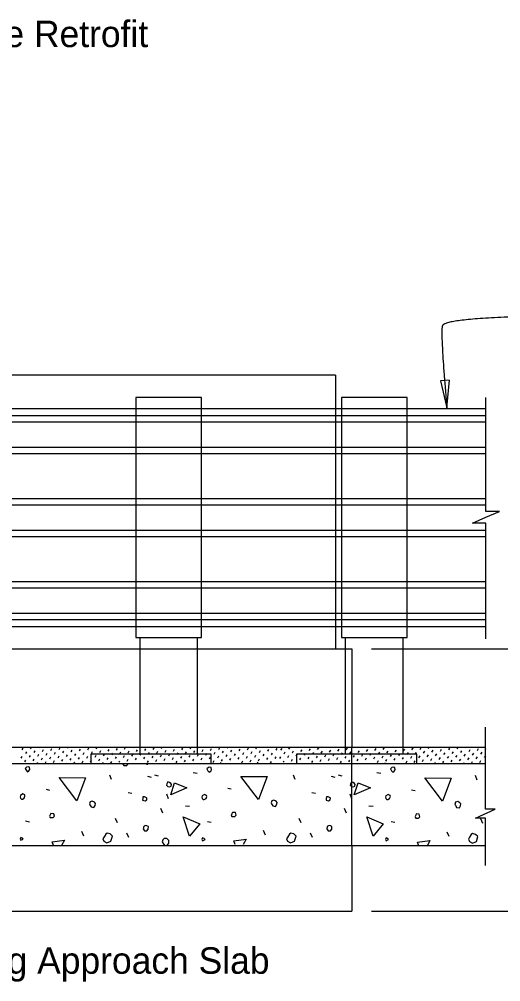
# Model space of a CAD drawing. Extents: x 1.5 to 68.7, y 0 to 31.1.
# Drawn here: x 34.15 to 37.81, y 9.2 to 16.53 of the extents above; entities that cross this region are included whole.
import ezdxf

# ---------------------------------------------------------------- set-up
doc = ezdxf.new("R2010")
doc.units = 0
for name, color, linetype in [('AdhocPoint_dp', 7, 'Continuous'), ('Patterning', 7, 'Continuous'), ('PlotBorder_dp', 7, 'Continuous'), ('SheetBorder_dp', 7, 'Continuous')]:
    doc.layers.add(name, color=color, linetype=linetype)

msp = doc.modelspace()

# ---------------------------------------------------------------- linework, layer by layer
at = {"layer": 'AdhocPoint_dp'}
for p, q in [((36.8263, 11.7345), (39.8006, 11.7345)), ((36.8263, 9.7345), (39.8006, 9.7345))]:
    msp.add_line(p, q, dxfattribs=at)
msp.add_lwpolyline([(37.4003, 13.5697), (37.4212, 13.7799), (37.3508, 13.775)], close=True, dxfattribs=at)
for points in [[(37.6978, 11.8101), (37.6978, 12.6907), (37.5945, 12.6907), (37.6978, 12.7357), (37.8012, 12.7807), (37.6978, 12.7807), (37.6978, 13.649)], [(37.6953, 10.0834), (37.6953, 10.4448), (37.6178, 10.4448), (37.7678, 10.5111), (37.6953, 10.5111), (37.6953, 11.1369)]]:
    msp.add_lwpolyline(points, dxfattribs=at)
msp.add_open_spline([(37.8896, 14.2621), (37.3828, 14.2426), (37.3496, 14.1481), (37.4003, 13.5697)], degree=2, dxfattribs=at)
at = {"layer": 'Patterning'}
for p, q in [((28.9195, 13.5645), (37.6978, 13.5645)), ((29.5771, 13.5123), (37.6978, 13.5123)), ((29.5783, 13.4641), (37.6978, 13.4641)), ((29.5831, 13.2713), (37.6978, 13.2713)), ((29.5842, 13.2231), (37.6978, 13.2231)), ((29.5807, 12.8791), (37.6978, 12.8791)), ((29.5795, 12.8309), (37.6978, 12.8309)), ((29.5747, 12.6381), (37.6978, 12.6381)), ((29.5735, 12.5899), (37.6978, 12.5899)), ((29.5831, 12.1978), (37.6978, 12.1978)), ((29.5842, 12.246), (37.6978, 12.246)), ((29.5771, 11.9567), (37.6978, 11.9567)), ((29.5783, 12.0049), (37.6978, 12.0049)), ((28.9195, 11.9044), (37.6978, 11.9044)), ((35.0654, 10.9324), (35.0654, 11.8211)), ((35.5029, 10.9324), (35.5029, 11.8211)), ((36.6296, 10.9324), (36.6296, 11.8211)), ((37.0671, 10.9324), (37.0671, 11.8211)), ((34.1686, 10.9633), (34.1767, 10.9773)), ((34.1963, 10.9356), (34.2044, 10.9496)), ((34.2321, 10.9714), (34.2397, 10.9845)), ((34.2598, 10.9437), (34.2679, 10.9577)), ((34.2875, 10.916), (34.2956, 10.93)), ((34.2956, 10.9795), (34.2985, 10.9845)), ((34.3233, 10.9518), (34.3314, 10.9658)), ((34.351, 10.9241), (34.3591, 10.9381)), ((34.3868, 10.9599), (34.3949, 10.9739)), ((34.4145, 10.9322), (34.4226, 10.9462)), ((34.4503, 10.968), (34.4584, 10.982)), ((34.478, 10.9403), (34.4861, 10.9543)), ((34.5057, 10.9126), (34.5138, 10.9266)), ((34.5138, 10.9761), (34.5186, 10.9845)), ((34.5415, 10.9484), (34.5496, 10.9624)), ((34.5692, 10.9207), (34.5773, 10.9347)), ((34.5773, 10.9842), (34.5774, 10.9845)), ((34.605, 10.9565), (34.6131, 10.9705)), ((34.6327, 10.9288), (34.6408, 10.9428)), ((34.6685, 10.9646), (34.6766, 10.9786)), ((34.6962, 10.9369), (34.7043, 10.9509)), ((34.732, 10.9727), (34.7388, 10.9845)), ((34.7597, 10.9451), (34.7678, 10.959)), ((34.7874, 10.9174), (34.7955, 10.9314)), ((34.7955, 10.9808), (34.7976, 10.9845)), ((34.8232, 10.9532), (34.8313, 10.9671)), ((34.8509, 10.9255), (34.859, 10.9395)), ((34.8867, 10.9613), (34.8948, 10.9753)), ((34.9118, 10.9343), (34.9199, 10.9483)), ((34.9476, 10.9701), (34.9557, 10.9841)), ((34.9753, 10.9424), (34.9834, 10.9564)), ((35.003, 10.9147), (35.0111, 10.9287)), ((35.0111, 10.9782), (35.0147, 10.9845)), ((35.0388, 10.9505), (35.0469, 10.9645)), ((35.0664, 10.9228), (35.0745, 10.9368)), ((35.1022, 10.9586), (35.1103, 10.9726)), ((35.1299, 10.9309), (35.138, 10.9449)), ((35.1657, 10.9667), (35.1738, 10.9807)), ((35.1934, 10.939), (35.2015, 10.953)), ((35.2292, 10.9748), (35.2348, 10.9845)), ((35.2569, 10.9471), (35.265, 10.9611)), ((35.2846, 10.9194), (35.2927, 10.9334)), ((35.2927, 10.9829), (35.2936, 10.9845)), ((35.3204, 10.9552), (35.3285, 10.9692)), ((35.3481, 10.9275), (35.3562, 10.9415)), ((35.3839, 10.9633), (35.392, 10.9773)), ((35.4116, 10.9356), (35.4197, 10.9496)), ((35.4474, 10.9714), (35.455, 10.9845)), ((35.4751, 10.9437), (35.4832, 10.9577)), ((35.5028, 10.916), (35.5109, 10.93)), ((35.5109, 10.9795), (35.5138, 10.9845)), ((35.5386, 10.9518), (35.5467, 10.9658)), ((35.5663, 10.9241), (35.5744, 10.9381)), ((35.6021, 10.9599), (35.6102, 10.9739)), ((35.6298, 10.9322), (35.6379, 10.9462)), ((35.6656, 10.968), (35.6737, 10.982)), ((35.6933, 10.9403), (35.7014, 10.9543)), ((35.721, 10.9126), (35.7291, 10.9266)), ((35.7291, 10.9761), (35.7339, 10.9845)), ((35.7568, 10.9484), (35.7649, 10.9624)), ((35.7845, 10.9207), (35.7926, 10.9347)), ((35.7926, 10.9842), (35.7927, 10.9845)), ((35.8203, 10.9565), (35.8284, 10.9705)), ((35.8479, 10.9288), (35.856, 10.9428)), ((35.8837, 10.9646), (35.8918, 10.9786)), ((35.9114, 10.9369), (35.9195, 10.9509)), ((35.9472, 10.9727), (35.954, 10.9845)), ((35.9749, 10.9451), (35.983, 10.959)), ((36.0026, 10.9174), (36.0107, 10.9314)), ((36.0107, 10.9808), (36.0128, 10.9845)), ((36.0384, 10.9532), (36.0465, 10.9671)), ((36.0661, 10.9255), (36.0742, 10.9395)), ((36.1019, 10.9613), (36.11, 10.9753)), ((36.1377, 10.9613), (36.1458, 10.9753)), ((36.1628, 10.9343), (36.1709, 10.9483)), ((36.1986, 10.9701), (36.2067, 10.9841)), ((36.2263, 10.9424), (36.2344, 10.9564)), ((36.254, 10.9147), (36.2621, 10.9287)), ((36.2898, 10.9505), (36.2979, 10.9645)), ((36.3175, 10.9228), (36.3256, 10.9368)), ((36.3533, 10.9586), (36.3614, 10.9726)), ((36.381, 10.9309), (36.3891, 10.9449)), ((36.4168, 10.9667), (36.4249, 10.9807)), ((36.4444, 10.939), (36.4526, 10.953)), ((36.5079, 10.9471), (36.516, 10.9611)), ((36.5356, 10.9194), (36.5437, 10.9334)), ((36.5714, 10.9552), (36.5795, 10.9692)), ((36.5991, 10.9275), (36.6072, 10.9415)), ((36.6349, 10.9633), (36.643, 10.9773)), ((36.6626, 10.9356), (36.6707, 10.9496)), ((36.7261, 10.9437), (36.7342, 10.9577)), ((36.7538, 10.916), (36.7619, 10.93)), ((36.7896, 10.9518), (36.7977, 10.9658)), ((36.8173, 10.9241), (36.8254, 10.9381)), ((36.8531, 10.9599), (36.8612, 10.9739)), ((36.8808, 10.9322), (36.8889, 10.9462)), ((36.9166, 10.968), (36.9247, 10.982)), ((36.9443, 10.9403), (36.9524, 10.9543)), ((36.972, 10.9126), (36.9801, 10.9266)), ((37.0078, 10.9484), (37.0159, 10.9624)), ((37.0355, 10.9207), (37.0436, 10.9347)), ((37.0713, 10.9565), (37.0794, 10.9705)), ((37.099, 10.9288), (37.1071, 10.9428)), ((37.1348, 10.9646), (37.1429, 10.9786)), ((37.16, 10.931), (37.1681, 10.945)), ((37.1958, 10.9668), (37.2039, 10.9808)), ((37.2235, 10.9391), (37.2316, 10.9531)), ((37.2593, 10.9749), (37.2649, 10.9845)), ((37.287, 10.9472), (37.2951, 10.9612)), ((37.3147, 10.9195), (37.3228, 10.9335)), ((37.3228, 10.983), (37.3237, 10.9845)), ((37.3505, 10.9553), (37.3586, 10.9693)), ((37.3782, 10.9276), (37.3863, 10.9416)), ((37.414, 10.9634), (37.4221, 10.9774)), ((37.4417, 10.9357), (37.4498, 10.9497)), ((37.4775, 10.9715), (37.485, 10.9845)), ((37.5052, 10.9438), (37.5133, 10.9578)), ((37.5329, 10.9161), (37.541, 10.9301)), ((37.541, 10.9796), (37.5438, 10.9845)), ((37.5687, 10.9519), (37.5768, 10.9659)), ((37.5964, 10.9242), (37.6045, 10.9382)), ((37.6322, 10.96), (37.6403, 10.974)), ((37.6599, 10.9323), (37.668, 10.9463)), ((37.6956, 10.9681), (37.6978, 10.9718)), ((34.1605, 10.8998), (34.1686, 10.9138)), ((34.1882, 10.8721), (34.1963, 10.8861)), ((34.224, 10.9079), (34.2321, 10.9219)), ((34.2517, 10.8802), (34.2598, 10.8942)), ((34.2834, 10.8595), (34.2875, 10.8665)), ((34.3152, 10.8883), (34.3233, 10.9023)), ((34.3429, 10.8606), (34.351, 10.8746)), ((34.3787, 10.8964), (34.3868, 10.9104)), ((34.4064, 10.8687), (34.4145, 10.8827)), ((34.4422, 10.9045), (34.4503, 10.9185)), ((34.4699, 10.8768), (34.478, 10.8908)), ((34.5036, 10.8595), (34.5057, 10.8631)), ((34.5334, 10.8849), (34.5415, 10.8989)), ((34.5624, 10.8595), (34.5692, 10.8712)), ((34.5969, 10.893), (34.605, 10.907)), ((34.6246, 10.8654), (34.6327, 10.8793)), ((34.6604, 10.9012), (34.6685, 10.9151)), ((34.6881, 10.8735), (34.6962, 10.8875)), ((34.7237, 10.8595), (34.7239, 10.8598)), ((34.7239, 10.9093), (34.732, 10.9232)), ((34.7516, 10.8816), (34.7597, 10.8956)), ((34.7825, 10.8595), (34.7874, 10.8679)), ((34.8151, 10.8897), (34.8232, 10.9037)), ((34.8428, 10.862), (34.8509, 10.876)), ((34.8786, 10.8978), (34.8867, 10.9118)), ((34.9062, 10.8701), (34.9113, 10.8788)), ((34.9395, 10.9066), (34.9476, 10.9206)), ((34.9672, 10.8789), (34.9753, 10.8929)), ((35.0306, 10.887), (35.0388, 10.901)), ((35.0941, 10.8951), (35.1022, 10.9091)), ((35.1218, 10.8674), (35.1299, 10.8814)), ((35.1576, 10.9032), (35.1657, 10.9172)), ((35.1853, 10.8755), (35.1934, 10.8895)), ((35.2211, 10.9113), (35.2292, 10.9253)), ((35.2488, 10.8836), (35.2569, 10.8976)), ((35.3123, 10.8917), (35.3204, 10.9057)), ((35.34, 10.864), (35.3481, 10.878)), ((35.3758, 10.8998), (35.3839, 10.9138)), ((35.3996, 10.8595), (35.4009, 10.8618)), ((35.4035, 10.8721), (35.4116, 10.8861)), ((35.4393, 10.9079), (35.4474, 10.9219)), ((35.467, 10.8802), (35.4751, 10.8942)), ((35.5305, 10.8883), (35.5386, 10.9023)), ((35.594, 10.8964), (35.6021, 10.9104)), ((35.6217, 10.8687), (35.6298, 10.8827)), ((35.6575, 10.9045), (35.6656, 10.9185)), ((35.6785, 10.8595), (35.6826, 10.8665)), ((35.6852, 10.8768), (35.6933, 10.8908)), ((35.7487, 10.8849), (35.7568, 10.8989)), ((35.8121, 10.893), (35.8203, 10.907)), ((35.8398, 10.8654), (35.8479, 10.8793)), ((35.8756, 10.9012), (35.8837, 10.9151)), ((35.8986, 10.8595), (35.9008, 10.8631)), ((35.9033, 10.8735), (35.9114, 10.8875)), ((35.9391, 10.9093), (35.9472, 10.9232)), ((35.9574, 10.8595), (35.9643, 10.8712)), ((35.9668, 10.8816), (35.9749, 10.8956)), ((36.0303, 10.8897), (36.0384, 10.9037)), ((36.058, 10.862), (36.0661, 10.876)), ((36.0938, 10.8978), (36.1019, 10.9118)), ((36.1296, 10.8978), (36.1377, 10.9118)), ((36.1573, 10.8701), (36.1623, 10.8788)), ((36.1905, 10.9066), (36.1986, 10.9206)), ((36.2182, 10.8789), (36.2263, 10.8929)), ((36.2817, 10.887), (36.2898, 10.901)), ((36.3452, 10.8951), (36.3533, 10.9091)), ((36.3729, 10.8674), (36.381, 10.8814)), ((36.4087, 10.9032), (36.4168, 10.9172)), ((36.4363, 10.8755), (36.4444, 10.8895)), ((36.4721, 10.9113), (36.4802, 10.9253)), ((36.4998, 10.8836), (36.5079, 10.8976)), ((36.5633, 10.8917), (36.5714, 10.9057)), ((36.591, 10.864), (36.5991, 10.878)), ((36.6268, 10.8998), (36.6349, 10.9138)), ((36.6506, 10.8595), (36.6519, 10.8618)), ((36.6545, 10.8721), (36.6626, 10.8861)), ((36.6903, 10.9079), (36.6984, 10.9219)), ((36.718, 10.8802), (36.7261, 10.8942)), ((36.7815, 10.8883), (36.7896, 10.9023)), ((36.845, 10.8964), (36.8531, 10.9104)), ((36.8727, 10.8687), (36.8808, 10.8827)), ((36.9085, 10.9045), (36.9166, 10.9185)), ((36.9295, 10.8595), (36.9336, 10.8665)), ((36.9362, 10.8768), (36.9443, 10.8908)), ((36.9997, 10.8849), (37.0078, 10.8989)), ((37.0632, 10.893), (37.0713, 10.907)), ((37.0909, 10.8654), (37.099, 10.8793)), ((37.1267, 10.9012), (37.1348, 10.9151)), ((37.1519, 10.8675), (37.16, 10.8815)), ((37.1877, 10.9033), (37.1958, 10.9173)), ((37.2154, 10.8756), (37.2235, 10.8896)), ((37.2499, 10.8595), (37.2512, 10.8619)), ((37.2512, 10.9114), (37.2593, 10.9254)), ((37.2789, 10.8837), (37.287, 10.8977)), ((37.3087, 10.8595), (37.3147, 10.87)), ((37.3424, 10.8918), (37.3505, 10.9058)), ((37.3701, 10.8641), (37.3782, 10.8781)), ((37.4059, 10.8999), (37.414, 10.9139)), ((37.4336, 10.8722), (37.4417, 10.8862)), ((37.4694, 10.908), (37.4775, 10.922)), ((37.4971, 10.8803), (37.5052, 10.8943)), ((37.5044, 10.8561), (37.5045, 10.8563)), ((37.5288, 10.8595), (37.5329, 10.8666)), ((37.5606, 10.8884), (37.5687, 10.9024)), ((37.5883, 10.8607), (37.5964, 10.8747)), ((37.6241, 10.8965), (37.6322, 10.9105)), ((37.6517, 10.8688), (37.6599, 10.8828)), ((37.6875, 10.9046), (37.6956, 10.9186)), ((35.4704, 10.7923), (35.5004, 10.787)), ((36.8675, 10.7923), (36.8975, 10.787)), ((34.849, 10.7375), (34.8366, 10.7711)), ((35.123, 10.764), (35.1513, 10.757)), ((35.1747, 10.7733), (35.203, 10.7662)), ((36.2461, 10.7375), (36.2337, 10.7711)), ((36.5201, 10.764), (36.5484, 10.757)), ((36.5718, 10.7733), (36.6001, 10.7662)), ((37.6297, 10.7341), (37.6173, 10.7677)), ((34.3505, 10.6633), (34.377, 10.658)), ((34.9763, 10.6385), (35.0028, 10.6332)), ((35.7329, 10.6715), (35.7594, 10.6662)), ((36.3734, 10.6385), (36.3999, 10.6332)), ((37.1312, 10.6598), (37.1577, 10.6545)), ((35.2808, 10.5921), (35.2684, 10.6257)), ((36.6779, 10.5921), (36.6655, 10.6257)), ((35.2384, 10.4825), (35.2242, 10.5179)), ((35.4103, 10.5378), (35.4421, 10.5342)), ((36.6355, 10.4825), (36.6213, 10.5179)), ((36.8074, 10.5378), (36.8392, 10.5342)), ((34.1949, 10.4229), (34.2232, 10.4158)), ((34.8932, 10.4069), (34.8791, 10.4423)), ((35.5782, 10.4193), (35.6065, 10.4122)), ((36.2903, 10.4069), (36.2762, 10.4423)), ((36.9753, 10.4193), (37.0036, 10.4122)), ((37.6739, 10.4035), (37.6597, 10.4389)), ((34.6369, 10.3062), (34.6227, 10.3415)), ((36.0192, 10.3144), (36.0051, 10.3497)), ((34.9803, 10.2951), (34.9661, 10.3305)), ((36.3774, 10.2951), (36.3632, 10.3305)), ((37.4176, 10.3027), (37.4034, 10.3381))]:
    msp.add_line(p, q, dxfattribs=at)
for points in [[(35.0342, 11.8211), (35.5342, 11.8211), (35.5342, 13.6478), (35.0342, 13.6478)], [(36.5984, 11.8211), (37.0984, 11.8211), (37.0984, 13.6478), (36.5984, 13.6478)], [(34.6907, 10.8595), (35.6073, 10.8595), (35.6073, 10.9324), (34.6907, 10.9324)], [(36.255, 10.8595), (37.1716, 10.8595), (37.1716, 10.9324), (36.255, 10.9324)]]:
    msp.add_lwpolyline(points, close=True, dxfattribs=at)
for points in [[(34.9311, 10.8594), (34.9409, 10.8436), (34.9639, 10.8453), (34.9728, 10.8542), (34.978, 10.8594)], [(35.1199, 10.8493), (35.1167, 10.8594)], [(35.1251, 10.8594), (35.1199, 10.8493)], [(34.1985, 10.8082), (34.2091, 10.7976), (34.2197, 10.8047), (34.2268, 10.8153), (34.2232, 10.833), (34.2144, 10.8347), (34.202, 10.833), (34.1914, 10.8224), (34.1985, 10.8082)], [(35.5818, 10.8047), (35.5924, 10.7941), (35.603, 10.8012), (35.61, 10.8118), (35.6065, 10.8294), (35.5977, 10.8312), (35.5853, 10.8294), (35.5747, 10.8188), (35.5818, 10.8047)], [(36.9788, 10.8047), (36.9894, 10.7941), (37.0001, 10.8012), (37.0071, 10.8118), (37.0036, 10.8294), (36.9948, 10.8312), (36.9824, 10.8294), (36.9718, 10.8188), (36.9788, 10.8047)], [(34.5856, 10.5766), (34.4513, 10.7534), (34.651, 10.7517), (34.5856, 10.5766)], [(35.2773, 10.6849), (35.2896, 10.6832), (35.302, 10.6885), (35.3055, 10.6991), (35.3002, 10.7079), (35.2896, 10.715), (35.2773, 10.7203), (35.2702, 10.7061), (35.2667, 10.6955), (35.2773, 10.6849)], [(35.2989, 10.6208), (35.3272, 10.7128), (35.4209, 10.6756), (35.2989, 10.6208)], [(35.968, 10.5849), (35.8336, 10.7616), (36.0334, 10.7599), (35.968, 10.5849)], [(36.6743, 10.6849), (36.6867, 10.6832), (36.6991, 10.6885), (36.7026, 10.6991), (36.6973, 10.7079), (36.6867, 10.715), (36.6743, 10.7203), (36.6673, 10.7061), (36.6637, 10.6955), (36.6743, 10.6849)], [(36.696, 10.6208), (36.7243, 10.7128), (36.818, 10.6756), (36.696, 10.6208)], [(37.3663, 10.5732), (37.2319, 10.75), (37.4317, 10.7482), (37.3663, 10.5732)], [(34.1631, 10.589), (34.1702, 10.589), (34.1843, 10.5961), (34.1896, 10.612), (34.1879, 10.6208), (34.1737, 10.6279), (34.1561, 10.6173), (34.1525, 10.6067), (34.1561, 10.5961), (34.1631, 10.589)], [(34.6846, 10.5448), (34.6935, 10.5289), (34.7147, 10.5254), (34.7235, 10.5413), (34.727, 10.5554), (34.7182, 10.5643), (34.7023, 10.5731), (34.6864, 10.5678), (34.6811, 10.5519), (34.6846, 10.5448)], [(35.0841, 10.5802), (35.1036, 10.5749), (35.116, 10.5837), (35.1177, 10.5961), (35.1142, 10.5996), (35.1, 10.6067), (35.0877, 10.6049), (35.0859, 10.5926), (35.0841, 10.5802)], [(35.5464, 10.5855), (35.5535, 10.5855), (35.5676, 10.5926), (35.5729, 10.6085), (35.5712, 10.6173), (35.557, 10.6244), (35.5393, 10.6138), (35.5358, 10.6032), (35.5393, 10.5926), (35.5464, 10.5855)], [(36.067, 10.553), (36.0758, 10.5371), (36.097, 10.5336), (36.1059, 10.5495), (36.1094, 10.5636), (36.1006, 10.5725), (36.0847, 10.5813), (36.0687, 10.576), (36.0634, 10.5601), (36.067, 10.553)], [(36.4812, 10.5802), (36.5007, 10.5749), (36.513, 10.5837), (36.5148, 10.5961), (36.5113, 10.5996), (36.4971, 10.6067), (36.4848, 10.6049), (36.483, 10.5926), (36.4812, 10.5802)], [(36.9435, 10.5855), (36.9506, 10.5855), (36.9647, 10.5926), (36.97, 10.6085), (36.9682, 10.6173), (36.9541, 10.6244), (36.9364, 10.6138), (36.9329, 10.6032), (36.9364, 10.5926), (36.9435, 10.5855)], [(37.4653, 10.5414), (37.4741, 10.5255), (37.4953, 10.5219), (37.5042, 10.5379), (37.5077, 10.552), (37.4989, 10.5608), (37.483, 10.5697), (37.4671, 10.5644), (37.4618, 10.5485), (37.4653, 10.5414)], [(35.7647, 10.4558), (35.7859, 10.4558), (35.7965, 10.4664), (35.7912, 10.4859), (35.7682, 10.4876), (35.7647, 10.477), (35.7594, 10.4682), (35.7647, 10.4558), (35.7612, 10.4593)], [(34.3823, 10.4476), (34.4035, 10.4476), (34.4141, 10.4582), (34.4088, 10.4777), (34.3859, 10.4794), (34.3823, 10.4688), (34.377, 10.46), (34.3823, 10.4476), (34.3788, 10.4511)], [(35.4417, 10.3075), (35.3939, 10.4542), (35.5194, 10.3994), (35.4417, 10.3075)], [(36.8387, 10.3075), (36.791, 10.4542), (36.9165, 10.3994), (36.8387, 10.3075)], [(37.163, 10.4442), (37.1842, 10.4442), (37.1948, 10.4548), (37.1895, 10.4742), (37.1665, 10.476), (37.163, 10.4654), (37.1577, 10.4565), (37.163, 10.4442), (37.1595, 10.4477)], [(35.0899, 10.3623), (35.0987, 10.3464), (35.1182, 10.3482), (35.127, 10.3605), (35.1288, 10.38), (35.1164, 10.3853), (35.1076, 10.3871), (35.0969, 10.3835), (35.0934, 10.38), (35.0899, 10.3623)], [(36.487, 10.3623), (36.4958, 10.3464), (36.5152, 10.3482), (36.5241, 10.3605), (36.5259, 10.38), (36.5135, 10.3853), (36.5046, 10.3871), (36.494, 10.3835), (36.4905, 10.38), (36.487, 10.3623)], [(34.1574, 10.2757), (34.1768, 10.2845), (34.1698, 10.2916), (34.1574, 10.2969), (34.1521, 10.2845), (34.1574, 10.2757)], [(34.4059, 10.2344), (34.3965, 10.2638), (34.4902, 10.2761), (34.4687, 10.2344)], [(34.7907, 10.2691), (34.8137, 10.2567), (34.8437, 10.2691), (34.8561, 10.3062), (34.8384, 10.3239), (34.8154, 10.3292), (34.8048, 10.3221), (34.7924, 10.3026), (34.7836, 10.2867), (34.7907, 10.2691)], [(35.2671, 10.2344), (35.2773, 10.2421), (35.2843, 10.2527), (35.2843, 10.2739), (35.2684, 10.2898), (35.249, 10.2881), (35.2401, 10.2792), (35.2348, 10.2633)], [(35.5407, 10.2721), (35.5601, 10.281), (35.553, 10.2881), (35.5407, 10.2934), (35.5354, 10.281), (35.5407, 10.2721)], [(35.7883, 10.2427), (35.7788, 10.272), (35.8725, 10.2843), (35.851, 10.2427)], [(36.1878, 10.2691), (36.2107, 10.2567), (36.2408, 10.2691), (36.2532, 10.3062), (36.2355, 10.3239), (36.2125, 10.3292), (36.2019, 10.3221), (36.1895, 10.3026), (36.1807, 10.2867), (36.1878, 10.2691)], [(36.9377, 10.2721), (36.9572, 10.281), (36.9501, 10.2881), (36.9377, 10.2934), (36.9324, 10.281), (36.9377, 10.2721)], [(37.1866, 10.231), (37.1771, 10.2603), (37.2708, 10.2727), (37.2494, 10.231)], [(37.5714, 10.2656), (37.5943, 10.2532), (37.6244, 10.2656), (37.6368, 10.3027), (37.6191, 10.3204), (37.5961, 10.3257), (37.5855, 10.3187), (37.5731, 10.2992), (37.5643, 10.2833), (37.5714, 10.2656)], [(35.2348, 10.2633), (35.2454, 10.2421), (35.2582, 10.2344)]]:
    msp.add_lwpolyline(points, dxfattribs=at)
at = {"layer": 'PlotBorder_dp'}
for p, q in [((36.5515, 13.8178), (26.2771, 13.8178)), ((36.5515, 13.8178), (36.5515, 11.7345)), ((26.2771, 11.7345), (36.6763, 11.7345)), ((36.5515, 11.7345), (36.6763, 11.7345)), ((36.6763, 11.7345), (36.6763, 10.9845)), ((27.4971, 10.9845), (37.6978, 10.9845)), ((36.6763, 10.2345), (36.6763, 10.9845)), ((28.2772, 10.8595), (34.2217, 10.8595)), ((34.2217, 10.8595), (37.6978, 10.8595)), ((31.4971, 10.2345), (37.6978, 10.2345)), ((36.6763, 10.2345), (36.6763, 9.7345)), ((27.4971, 9.7345), (36.6763, 9.7345))]:
    msp.add_line(p, q, dxfattribs=at)

# ---------------------------------------------------------------- texts
at = {"layer": 'AdhocPoint_dp'}
msp.add_text('Parallel Portion of Vertical Face Retrofit ', height=0.2016, dxfattribs=at).set_placement((30.4075, 16.3181))
at = {"layer": 'SheetBorder_dp'}
msp.add_text('Existing Approach Slab', height=0.2016, dxfattribs=at).set_placement((33.2635, 9.2581))

doc.saveas('drawing.dxf')
